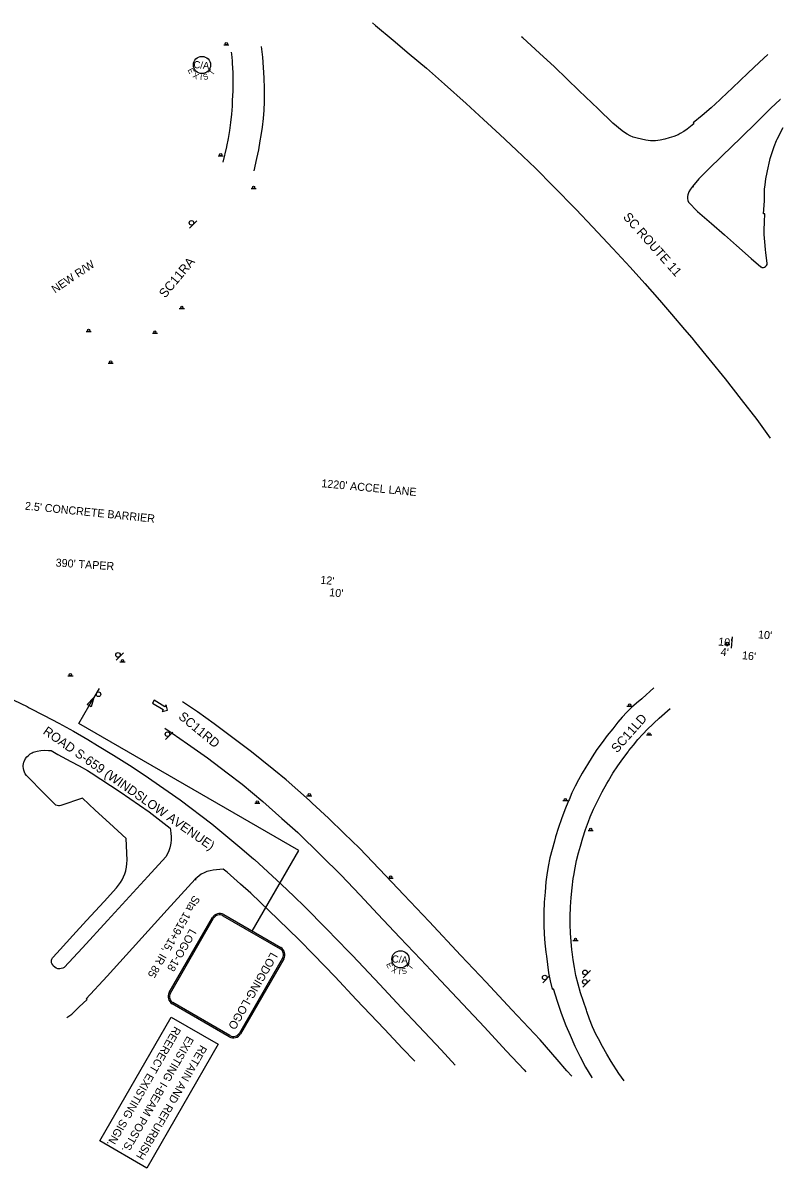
# Model space of a CAD drawing. Extents: x 1798880 to 1800499, y 1187704 to 1188705.
# Drawn here: x 1799253 to 1799916, y 1187704 to 1188705 of the extents above; entities that cross this region are included whole.
import ezdxf

# ---------------------------------------------------------------- set-up
doc = ezdxf.new("R2010")
doc.units = 0
for name, color, linetype in [('RD_EX_Road', 7, 'Continuous'), ('RD_PD_Final_LnLine', 7, 'Continuous'), ('RD_PD_Final_TX', 7, 'Continuous'), ('RD_PD_RW_TX', 7, 'Continuous'), ('RD_Sketch8', 7, 'Continuous'), ('RD_TX_RoadID', 7, 'Continuous'), ('SN_P_Signs', 7, 'Continuous')]:
    doc.layers.add(name, color=color, linetype=linetype)

# ---------------------------------------------------------------- blocks, each defined once
blk = doc.blocks.new('SARRW2')
at = {"layer": 'RD_PD_Final_LnLine'}
blk.add_lwpolyline([(-12, 1.2), (-12, -1.2), (-2.83, -1.2), (-2.83, -2.83), (0, 0), (-2.83, 2.83), (-2.83, 1.2)], close=True, dxfattribs=at)

msp = doc.modelspace()

# ---------------------------------------------------------------- linework, layer by layer
at = {"layer": 'RD_EX_Road'}
for points in [[(1799559.1, 1188705.5), (1799561.7, 1188703.3), (1799577.3, 1188690.3), (1799591.3, 1188678.5), (1799606.3, 1188665.9), (1799622.1, 1188652), (1799641.1, 1188635), (1799656.2, 1188621.1), (1799670.6, 1188608), (1799685.2, 1188594.3), (1799701.6, 1188578.4), (1799717.1, 1188562.8), (1799737.2, 1188542.3), (1799751.7, 1188527.3), (1799769.4, 1188508.3), (1799784.4, 1188492), (1799797.3, 1188477.6), (1799810.2, 1188463), (1799820.8, 1188450.8), (1799832.1, 1188437.5), (1799838.5, 1188430), (1799841.7, 1188426), (1799853.3, 1188411.9), (1799867.7, 1188394.2), (1799881.7, 1188376.3), (1799895.2, 1188358.7), (1799907, 1188342.3)], [(1799905, 1188677.7), (1799897.5, 1188671), (1799887.4, 1188661.6), (1799874, 1188648.8), (1799864.1, 1188639.4), (1799862.9, 1188638.3), (1799855.3, 1188631.2), (1799847.6, 1188624.5), (1799839.5, 1188618), (1799840.2, 1188617.3), (1799837.4, 1188614.8), (1799834.5, 1188612.6), (1799831.5, 1188610.5), (1799828.3, 1188608.7), (1799826.4, 1188607.7), (1799822.6, 1188606.2), (1799818.7, 1188604.9), (1799814.7, 1188603.8), (1799810.7, 1188603), (1799806.6, 1188602.4), (1799806.1, 1188602.3), (1799802.2, 1188602.5), (1799798.3, 1188603), (1799794.4, 1188603.7), (1799790.6, 1188604.6), (1799787, 1188605.7), (1799784.4, 1188606.8), (1799781.9, 1188608.1), (1799779.6, 1188609.6), (1799777.4, 1188611.2), (1799769.5, 1188617.8), (1799756.4, 1188630.3), (1799739.9, 1188646.2), (1799718.2, 1188667), (1799705.3, 1188679.1), (1799690.5, 1188692.5), (1799689.6, 1188693.3)], [(1799435.6, 1188679.8), (1799435.8, 1188678.1), (1799436.4, 1188672.4), (1799436.5, 1188670), (1799436.9, 1188662), (1799437, 1188653.9), (1799436.9, 1188645.9), (1799436.5, 1188637.8), (1799436.3, 1188632.8), (1799435.8, 1188625.7), (1799435.1, 1188618.5), (1799434.1, 1188611.5), (1799432.9, 1188604.4), (1799431.5, 1188597.4), (1799431.4, 1188597.1), (1799428.3, 1188583.8)], [(1799455.6, 1188576.1), (1799458.1, 1188586.9), (1799459.7, 1188594.6), (1799461, 1188602.4), (1799461.8, 1188607.1), (1799462.9, 1188614.4), (1799463.7, 1188621.8), (1799464.3, 1188629.2), (1799464.6, 1188636.6), (1799464.7, 1188644), (1799464.6, 1188648.1), (1799464.4, 1188657.3), (1799463.8, 1188666.5), (1799463.1, 1188675.6), (1799462.1, 1188684.8)], [(1799916.1, 1188638.6), (1799915.6, 1188638.6), (1799907.5, 1188630.8), (1799895.4, 1188618.7), (1799881.4, 1188605.1), (1799865, 1188589.2), (1799852.6, 1188577.4), (1799844.6, 1188569), (1799839.1, 1188562.4)], [(1799839.9, 1188561.8), (1799839.1, 1188562.4), (1799837.3, 1188560), (1799835.9, 1188557.7), (1799835.5, 1188556.8), (1799834.9, 1188555.2), (1799834.7, 1188553.6), (1799834.6, 1188551.9), (1799834.9, 1188550.3), (1799835.4, 1188548.6), (1799843.5, 1188540.6), (1799855.7, 1188530), (1799866.9, 1188520.1), (1799877.5, 1188510.8), (1799890.3, 1188499.5), (1799898.7, 1188492.3), (1799899, 1188492.1), (1799900, 1188491.7), (1799901, 1188491.7), (1799902.1, 1188491.9), (1799903, 1188492.4), (1799903.7, 1188493.3), (1799904.2, 1188494.2), (1799904.3, 1188495.3), (1799903.2, 1188504.3), (1799902.8, 1188507.4), (1799902.2, 1188514), (1799901.8, 1188520.6), (1799901.8, 1188524.4), (1799901.9, 1188531.4), (1799902.2, 1188538.4), (1799901.2, 1188538.4), (1799901.9, 1188549.9), (1799902.1, 1188560), (1799902.5, 1188563.8), (1799903.2, 1188569.2), (1799904.2, 1188574.7), (1799905.4, 1188580.1), (1799905.7, 1188581.5), (1799907.1, 1188586.9), (1799908.7, 1188592.2), (1799910.5, 1188597.4), (1799912.6, 1188602.6), (1799913.1, 1188603.7), (1799918.2, 1188614.1)], [(1799805.2, 1188124), (1799795.1, 1188114.9), (1799794.7, 1188114.5), (1799790.2, 1188110.8), (1799785.8, 1188106.8), (1799781.6, 1188102.7), (1799777.6, 1188098.4), (1799773.8, 1188094), (1799770.1, 1188089.4), (1799769.3, 1188088.4), (1799764.5, 1188082.4), (1799759.9, 1188076.3), (1799755.5, 1188070.1), (1799751.2, 1188063.7), (1799747.2, 1188057.2), (1799745.7, 1188054.9), (1799742.4, 1188049.4), (1799739.3, 1188043.7), (1799736.3, 1188038), (1799733.6, 1188032.2), (1799731.1, 1188026.2), (1799730.7, 1188025.2), (1799727.5, 1188017.5), (1799724.6, 1188009.7), (1799721.8, 1188001.9), (1799719.3, 1187993.9), (1799718.2, 1187990.1), (1799716.2, 1187982.8), (1799714.4, 1187975.4), (1799712.9, 1187968), (1799711.6, 1187960.5), (1799710.9, 1187954.4), (1799710.1, 1187945.5), (1799709.4, 1187936.6), (1799709, 1187927.7), (1799709, 1187924.5), (1799709.1, 1187916.6), (1799709.4, 1187908.7), (1799710, 1187900.8), (1799710.8, 1187892.9), (1799711.2, 1187889.5), (1799712.1, 1187882.3), (1799713.2, 1187875), (1799714.6, 1187867.9), (1799716.2, 1187860.7), (1799717.3, 1187861.1), (1799720.6, 1187850.3), (1799724.2, 1187839.6), (1799728.3, 1187829), (1799731.9, 1187820.4), (1799736.1, 1187810.9), (1799740.7, 1187801.6), (1799745.6, 1187792.4), (1799750.9, 1187783.5), (1799751.2, 1187783.1)], [(1799245.5, 1188113.4), (1799257, 1188107.7), (1799259, 1188106.7), (1799272, 1188100), (1799284.9, 1188093.2), (1799297.7, 1188086.1), (1799310.3, 1188078.8), (1799318.7, 1188073.8), (1799332.7, 1188065.2), (1799346.6, 1188056.4), (1799360.3, 1188047.4), (1799366.2, 1188043.5), (1799390.8, 1188026.3), (1799418.7, 1188005.1), (1799430.9, 1187995.1), (1799443.1, 1187984.9), (1799455.1, 1187974.6), (1799455.9, 1187973.9), (1799467.6, 1187963.3), (1799479.3, 1187952.6), (1799490.7, 1187941.7), (1799499.6, 1187933), (1799519, 1187913.5), (1799538.1, 1187893.7), (1799541.6, 1187890), (1799565.5, 1187864.6), (1799584.3, 1187844.7), (1799599.7, 1187828.3), (1799619.3, 1187807.5), (1799631.6, 1187794.3)], [(1799733.4, 1187784.7), (1799729.1, 1187789.2), (1799720.6, 1187799.2), (1799705.8, 1187816.4), (1799680.9, 1187842.5), (1799658.6, 1187866.7), (1799636.3, 1187890), (1799608.6, 1187919.7), (1799586.6, 1187943.1), (1799570.9, 1187959.7), (1799547.8, 1187983.8), (1799534.5, 1187996.9), (1799520.6, 1188010.2), (1799506.5, 1188023.4), (1799504.2, 1188025.5), (1799494, 1188034.6), (1799483.6, 1188043.6), (1799473, 1188052.4), (1799462.3, 1188061), (1799453.2, 1188068.1), (1799437.1, 1188080.5), (1799420.8, 1188092.7), (1799406.1, 1188103), (1799393, 1188111.8)], [(1799779.3, 1187780.4), (1799774.6, 1187786.8), (1799767.9, 1187797.4), (1799764, 1187803.8), (1799760.2, 1187810.4), (1799756.7, 1187817.1), (1799754.6, 1187821.3), (1799751.7, 1187827.8), (1799749, 1187834.4), (1799746.6, 1187841), (1799746.2, 1187842.3), (1799743.6, 1187849.8), (1799741.2, 1187857.4), (1799739, 1187865.1), (1799737.1, 1187872.7), (1799735.7, 1187879.5), (1799734.6, 1187886.4), (1799733.7, 1187893.2), (1799733.6, 1187895), (1799732.8, 1187902.3), (1799732.3, 1187909.7), (1799732.1, 1187917.1), (1799732, 1187924.1), (1799732.4, 1187932.5), (1799733, 1187940.9), (1799733.8, 1187949.2), (1799734.8, 1187957.5), (1799735.2, 1187959.9), (1799736.3, 1187966.6), (1799737.7, 1187973.2), (1799739.4, 1187979.8), (1799741, 1187985.7), (1799743.1, 1187993), (1799745.4, 1188000.2), (1799748, 1188007.3), (1799749.5, 1188011.2), (1799752.4, 1188018), (1799756.1, 1188025.6), (1799760, 1188033.1), (1799764.1, 1188040.4), (1799765.6, 1188042.8), (1799769.5, 1188049.4), (1799773.7, 1188055.8), (1799778.1, 1188062), (1799782.7, 1188068.2), (1799783.5, 1188069.2), (1799787.3, 1188074.1), (1799791.3, 1188078.9), (1799795.5, 1188083.6), (1799799.8, 1188088), (1799804.4, 1188092.4), (1799805.2, 1188093.1), (1799810, 1188097.7), (1799819.4, 1188106.1)], [(1799377.4, 1188088.8), (1799384, 1188084.4), (1799397.3, 1188075.2), (1799414.9, 1188062.9), (1799432, 1188049.9), (1799445.2, 1188039.8), (1799463.1, 1188024.8), (1799479.9, 1188010), (1799493.9, 1187997.5), (1799514.2, 1187977.5), (1799531.8, 1187960.3), (1799548, 1187943), (1799563.7, 1187926.3), (1799583.1, 1187905.8), (1799601.5, 1187886.5), (1799618.9, 1187868), (1799638.1, 1187847.6), (1799657.1, 1187827.3), (1799676, 1187806.7), (1799691.7, 1187790.1), (1799693.2, 1187788.5)], [(1799255.6, 1188062.3), (1799256.8, 1188063.8), (1799258.2, 1188065.1), (1799259.7, 1188066.3), (1799261.4, 1188067.3), (1799262.5, 1188067.8), (1799265.8, 1188068.7), (1799269.1, 1188069.3)], [(1799269.1, 1188069.3), (1799272.4, 1188069.5), (1799275.7, 1188069.4), (1799278, 1188069.2), (1799283.8, 1188065.9), (1799295.2, 1188059.8), (1799302.7, 1188056), (1799309.8, 1188051.8), (1799313, 1188049.9), (1799338.5, 1188033.2), (1799363.9, 1188015.6), (1799382.3, 1188001.5), (1799382.6, 1187999.8), (1799382.9, 1187996.9), (1799383, 1187994), (1799383, 1187991.1), (1799382.7, 1187988.2), (1799382.5, 1187986.9), (1799381.8, 1187984.2), (1799380.9, 1187981.5), (1799379.8, 1187978.9), (1799378.5, 1187976.5)], [(1799378.5, 1187976.5), (1799362.6, 1187959.2), (1799343.4, 1187938.1), (1799327.4, 1187920.7), (1799305.5, 1187896.7), (1799289.5, 1187879.6), (1799288.3, 1187879), (1799287, 1187878.6), (1799285.7, 1187878.4), (1799284.3, 1187878.4), (1799283.9, 1187878.5), (1799282.6, 1187879.1), (1799281.4, 1187879.8), (1799280.3, 1187880.8), (1799279.5, 1187881.9), (1799278.8, 1187883.1), (1799278.5, 1187883.6), (1799278.4, 1187884.7), (1799278.5, 1187885.9), (1799278.8, 1187887), (1799279.4, 1187888), (1799279.8, 1187888.6), (1799286, 1187895.3), (1799297, 1187907.5), (1799309, 1187920.8), (1799324.5, 1187937.4), (1799335.3, 1187949.3), (1799337.1, 1187951.5), (1799338.8, 1187953.8), (1799340.2, 1187956.3), (1799341.5, 1187958.8), (1799342.5, 1187961.5), (1799343.4, 1187964.2), (1799343.4, 1187964.3), (1799344, 1187967.3), (1799344.4, 1187970.4), (1799344.6, 1187973.4), (1799344.6, 1187973.5), (1799343.7, 1187992.4), (1799329, 1188005.9), (1799316.7, 1188017.2), (1799305.4, 1188027.6), (1799286.6, 1188021.1), (1799285.5, 1188020.9), (1799284.4, 1188020.9), (1799283.3, 1188021.1), (1799282.3, 1188021.6), (1799281.9, 1188021.9), (1799272.6, 1188031.2), (1799256.5, 1188047.5), (1799255.5, 1188048.9), (1799254.7, 1188050.4), (1799254.1, 1188052), (1799253.8, 1188053.7), (1799253.6, 1188055.4), (1799253.7, 1188056.1), (1799253.9, 1188057.6), (1799254.3, 1188059), (1799254.6, 1188059.7), (1799255.7, 1188062.2)], [(1799596.1, 1187797.6), (1799585.3, 1187808.9), (1799569.7, 1187825.6), (1799544.9, 1187851.7), (1799526.5, 1187871.3), (1799507.5, 1187891.1), (1799495, 1187903.8), (1799476.7, 1187921.7), (1799452.7, 1187944.6), (1799443.8, 1187952.6), (1799432, 1187962.9), (1799428.6, 1187965.5), (1799419.8, 1187964.7), (1799417.1, 1187964.2), (1799414.4, 1187963.5), (1799411.8, 1187962.5), (1799409.4, 1187961.3), (1799404.2, 1187956.7)], [(1799291.8, 1187835.8), (1799296.1, 1187838.9), (1799302.7, 1187845.2), (1799309.5, 1187851.5), (1799308.8, 1187852.2), (1799327.2, 1187872), (1799379.7, 1187929.9), (1799404.2, 1187956.7), (1799404.9, 1187956)]]:
    msp.add_lwpolyline(points, dxfattribs=at)
at = {"layer": 'RD_Sketch8'}
for centre in [(1799410, 1188668.7), (1799583.6, 1187886.8)]:
    msp.add_circle(centre, 7.5, dxfattribs=at)
at = {"layer": 'SN_P_Signs'}
for p, q in [((1799429.1, 1188686.2), (1799433.6, 1188686.2)), ((1799424.1, 1188589.3), (1799428.6, 1188589.3)), ((1799452.9, 1188560.7), (1799457.4, 1188560.7)), ((1799399.1, 1188526.1), (1799405.5, 1188532.5)), ((1799390.1, 1188455.9), (1799394.6, 1188455.9)), ((1799308.7, 1188435.6), (1799313.2, 1188435.6)), ((1799366.6, 1188434.2), (1799371.1, 1188434.2)), ((1799327.9, 1188408), (1799332.4, 1188408)), ((1799867.1, 1188161.9), (1799871.6, 1188161.9)), ((1799873.2, 1188158.7), (1799874.1, 1188168.7)), ((1799334.9, 1188148.3), (1799341.3, 1188154.6)), ((1799338.3, 1188146.8), (1799342.8, 1188146.8)), ((1799292.8, 1188134.6), (1799297.3, 1188134.6)), ((1799320, 1188123.4), (1799315.5, 1188115.6)), ((1799302.4, 1188093), (1799315.5, 1188115.6)), ((1799781.7, 1188108), (1799786.2, 1188108)), ((1799494.7, 1187982), (1799302.4, 1188093)), ((1799378.2, 1188079), (1799384.5, 1188085.4)), ((1799798.9, 1188082.9), (1799803.4, 1188082.9)), ((1799501.5, 1188029.6), (1799506, 1188029.6)), ((1799456.1, 1188023.3), (1799460.6, 1188023.3)), ((1799725.6, 1188025.5), (1799730.1, 1188025.5)), ((1799747.7, 1187999.5), (1799752.2, 1187999.5)), ((1799453.9, 1187911.4), (1799494.7, 1187982)), ((1799572.7, 1187957.7), (1799577.2, 1187957.7)), ((1799734.5, 1187903.3), (1799739, 1187903.3)), ((1799708.1, 1187866.3), (1799714.4, 1187872.6)), ((1799743.1, 1187862.5), (1799749.5, 1187868.8)), ((1799743.3, 1187870.7), (1799749.7, 1187877.1)), ((1799320.6, 1187728), (1799383.1, 1187836.3)), ((1799383.1, 1187836.3), (1799424.3, 1187812.5)), ((1799424.3, 1187812.5), (1799361.8, 1187704.2)), ((1799361.8, 1187704.2), (1799320.6, 1187728))]:
    msp.add_line(p, q, dxfattribs=at)
msp.add_lwpolyline([(1799309.6, 1188109.6), (1799315.5, 1188115.6), (1799313.1, 1188107.5)], close=True, dxfattribs=at)
for points in [[(1799381.4, 1187857.7), (1799419.2, 1187923.2)], [(1799382.4, 1187857.1), (1799420.2, 1187922.6)], [(1799428.4, 1187924.7), (1799478.3, 1187896)], [(1799429, 1187925.8), (1799478.9, 1187897)], [(1799480.5, 1187887.8), (1799442.7, 1187822.3)], [(1799481.5, 1187887.2), (1799443.7, 1187821.7)], [(1799434.5, 1187820.1), (1799384.6, 1187848.9)], [(1799433.9, 1187819), (1799384, 1187847.8)]]:
    msp.add_lwpolyline(points, dxfattribs=at)
for centre, radius in [((1799431.3, 1188687.2), 1), ((1799426.4, 1188590.3), 1), ((1799455.1, 1188561.7), 1), ((1799400.9, 1188530.7), 2), ((1799392.4, 1188456.9), 1), ((1799310.9, 1188436.6), 1), ((1799368.8, 1188435.2), 1), ((1799330.1, 1188409.1), 1), ((1799869.4, 1188162.9), 1), ((1799336.6, 1188152.9), 2), ((1799340.5, 1188147.8), 1), ((1799295, 1188135.6), 1), ((1799319.5, 1188118.5), 2), ((1799784, 1188109), 1), ((1799379.9, 1188083.6), 2), ((1799801.1, 1188083.9), 1), ((1799503.8, 1188030.6), 1), ((1799458.4, 1188024.4), 1), ((1799727.9, 1188026.5), 1), ((1799750, 1188000.5), 1), ((1799575, 1187958.7), 1), ((1799736.7, 1187904.3), 1), ((1799709.8, 1187870.9), 2), ((1799744.9, 1187867.1), 2), ((1799745.1, 1187875.3), 2)]:
    msp.add_circle(centre, radius, dxfattribs=at)
for centre, radius, start, end in [((1799425.4, 1187919.6), 7.2, 60.0034, 150.0034), ((1799425.4, 1187919.6), 6, 60.0034, 150.0034), ((1799475.3, 1187890.8), 6, 330.0034, 60.0034), ((1799475.3, 1187890.8), 7.2, 330.0034, 60.0034), ((1799387.6, 1187854.1), 7.2, 150.0034, 240.0034), ((1799387.6, 1187854.1), 6, 150.0034, 240.0034), ((1799437.5, 1187825.3), 7.2, 240.0034, 330.0034), ((1799437.5, 1187825.3), 6, 240.0034, 330.0034)]:
    msp.add_arc(centre, radius, start, end, dxfattribs=at)

# ---------------------------------------------------------------- block references
at = {"layer": 'RD_PD_Final_LnLine', "xscale": 1.2000000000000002, "yscale": 1.200000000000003, "rotation": -31.48267548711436}
msp.add_blockref('SARRW2', (1799379.8, 1188104.5), dxfattribs=at)

# ---------------------------------------------------------------- texts
at = {"layer": 'RD_PD_Final_TX'}
for s, rotation, p in [("1220' ACCEL LANE", 354.6557, (1799514.2, 1188299.6)), ("2.5' CONCRETE BARRIER", 354.2763, (1799254.9, 1188279.9)), ("390' TAPER", 356.3368, (1799281.9, 1188230.2)), ("12'", 354.6557, (1799513.3, 1188215.2)), ("10'", 354.6557, (1799521.1, 1188204.3)), ("10'", 354.6557, (1799896.1, 1188167.5)), ("10'", 354.6557, (1799861.3, 1188161.2)), ("4'", 354.6557, (1799863.4, 1188152.2)), ("16'", 354.6557, (1799882.1, 1188149.2))]:
    msp.add_text(s, height=7, rotation=rotation, dxfattribs=at).set_placement(p)
at = {"layer": 'RD_PD_RW_TX'}
msp.add_text('NEW R/W', height=7, rotation=33.8224, dxfattribs=at).set_placement((1799281.4, 1188468.9))
at = {"layer": 'RD_Sketch8'}
for s, height, rotation, p in [('C/A', 6.25, 354.9057, (1799402.3, 1188666.1)), ('E', 5, 298.1169, (1799397.3, 1188664.3)), ('X', 5, 330.5463, (1799401.5, 1188658.2)), ('I', 5, 354.7063, (1799408.1, 1188655.6)), ('S', 5, 16.6981, (1799411.8, 1188655.4)), ('T', 5, 53.0908, (1799419.3, 1188659.1)), ('C/A', 6.25, 354.9057, (1799575.9, 1187884.2)), ('E', 5, 298.1169, (1799570.9, 1187882.3)), ('X', 5, 330.5463, (1799575.2, 1187876.3)), ('I', 5, 354.7063, (1799581.8, 1187873.6)), ('S', 5, 16.6981, (1799585.4, 1187873.5)), ('T', 5, 53.0908, (1799593, 1187877.2))]:
    msp.add_text(s, height=height, rotation=rotation, dxfattribs=at).set_placement(p)
at = {"layer": 'RD_TX_RoadID'}
for s, rotation, p in [('SC ROUTE 11', 311.6201, (1799777.8, 1188535.4)), ('SC11RA', 50.2763, (1799377.8, 1188464.4)), ('SC11RD', 320.6335, (1799388.8, 1188097.8)), ('SC11LD', 48.6434, (1799773.1, 1188066.7)), ('ROAD S-659 (WINDSLOW AVENUE)', 325.1147, (1799270.3, 1188084.4))]:
    msp.add_text(s, height=8, rotation=rotation, dxfattribs=at).set_placement(p)
at = {"layer": 'SN_P_Signs'}
for s, height, p in [('Sta 1519+15, IR 85', 7, (1799402.7, 1187943.2)), ('LOGO-18', 7, (1799399.5, 1187913.9)), ('LODGING-LOGO', 7.2, (1799470.4, 1187893.4)), ('REERECT EXISTING SIGN.', 7, (1799386, 1187828.7)), ('EXISTING I-BEAM POSTS.', 7, (1799397.2, 1187820.2)), ('RETAIN AND REFURBISH', 7, (1799408.8, 1187812.4))]:
    msp.add_text(s, height=height, rotation=240.0034, dxfattribs=at).set_placement(p)

doc.saveas('drawing.dxf')
